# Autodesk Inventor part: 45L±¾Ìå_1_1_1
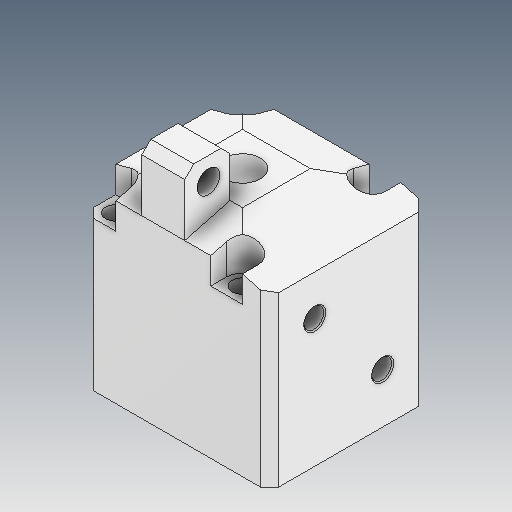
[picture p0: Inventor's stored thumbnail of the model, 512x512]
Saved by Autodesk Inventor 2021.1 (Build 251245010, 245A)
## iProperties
Created: 2021-05
Part Number: 45L±¾Ìå_1_1_1
Material: Ogólny
Document SubType Name: Modeling
Designer: user
Density: 1 g/cm^3
Appearance: Domyślna
Author: user
Revision Number: ÈÎºÎ
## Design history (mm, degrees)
feature "ÊäÈë1"
feature "ÊäÈë2"
node "Bryła1"
node "Bryła2"
